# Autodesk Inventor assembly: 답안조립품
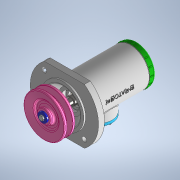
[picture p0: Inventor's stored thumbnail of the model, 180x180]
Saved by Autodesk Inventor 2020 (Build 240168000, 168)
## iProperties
Created: 2022-05
Part Number: 답안조립품
Document SubType Name: Assembly
Designer: Student
Author: Student
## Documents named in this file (21)
- C:\Users\Student\Desktop\720506V1025\답안조립품.iam
- C:\Users\Student\Desktop\720506V1025\본체.ipt
- C:\Users\Student\Desktop\720506V1025\개스킷.ipt
- C:\Users\Student\Desktop\720506V1025\사이드 커버.ipt
- 사이드 커버.ipt
- C:\Users\Student\Desktop\720506V1025\축.ipt
- C:\Users\Student\Desktop\720506V1025\멈춤링 15 x 1.ipt
- C:\Users\Student\Desktop\720506V1025\베어링 6202.ipt
- C:\Users\Student\Desktop\720506V1025\멈춤링 35 x 1.6.ipt
- C:\Users\Student\Desktop\720506V1025\부시1.ipt
- C:\Users\Student\Desktop\720506V1025\부시2.ipt
- C:\Users\Student\Desktop\720506V1025\와셔 10 x 21.ipt
- C:\Users\Student\Desktop\720506V1025\너트 M10.ipt
- C:\Users\Student\Desktop\720506V1025\V-벨트풀리.ipt
- C:\Users\Student\Desktop\720506V1025\키 4 x 4.ipt
- C:\Users\Student\Desktop\720506V1025\와셔 4 x 16.ipt
- C:\Users\Student\Desktop\720506V1025\멈춤나사 M3.ipt
- C:\Users\Student\Desktop\720506V1025\볼트 M4 x 10.ipt
- C:\Users\Student\Desktop\720506V1025\탑 커버.ipt
- C:\Users\Student\Desktop\720506V1025\십자볼트 M3 x 10.ipt
- C:\Users\Student\Desktop\720506V1025\와셔 3 x 6.ipt
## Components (3 placed, 3 different names)
1. 개스킷:1
2. V-벨트풀리:1
3. ISO 4017 M4 x 10:1
